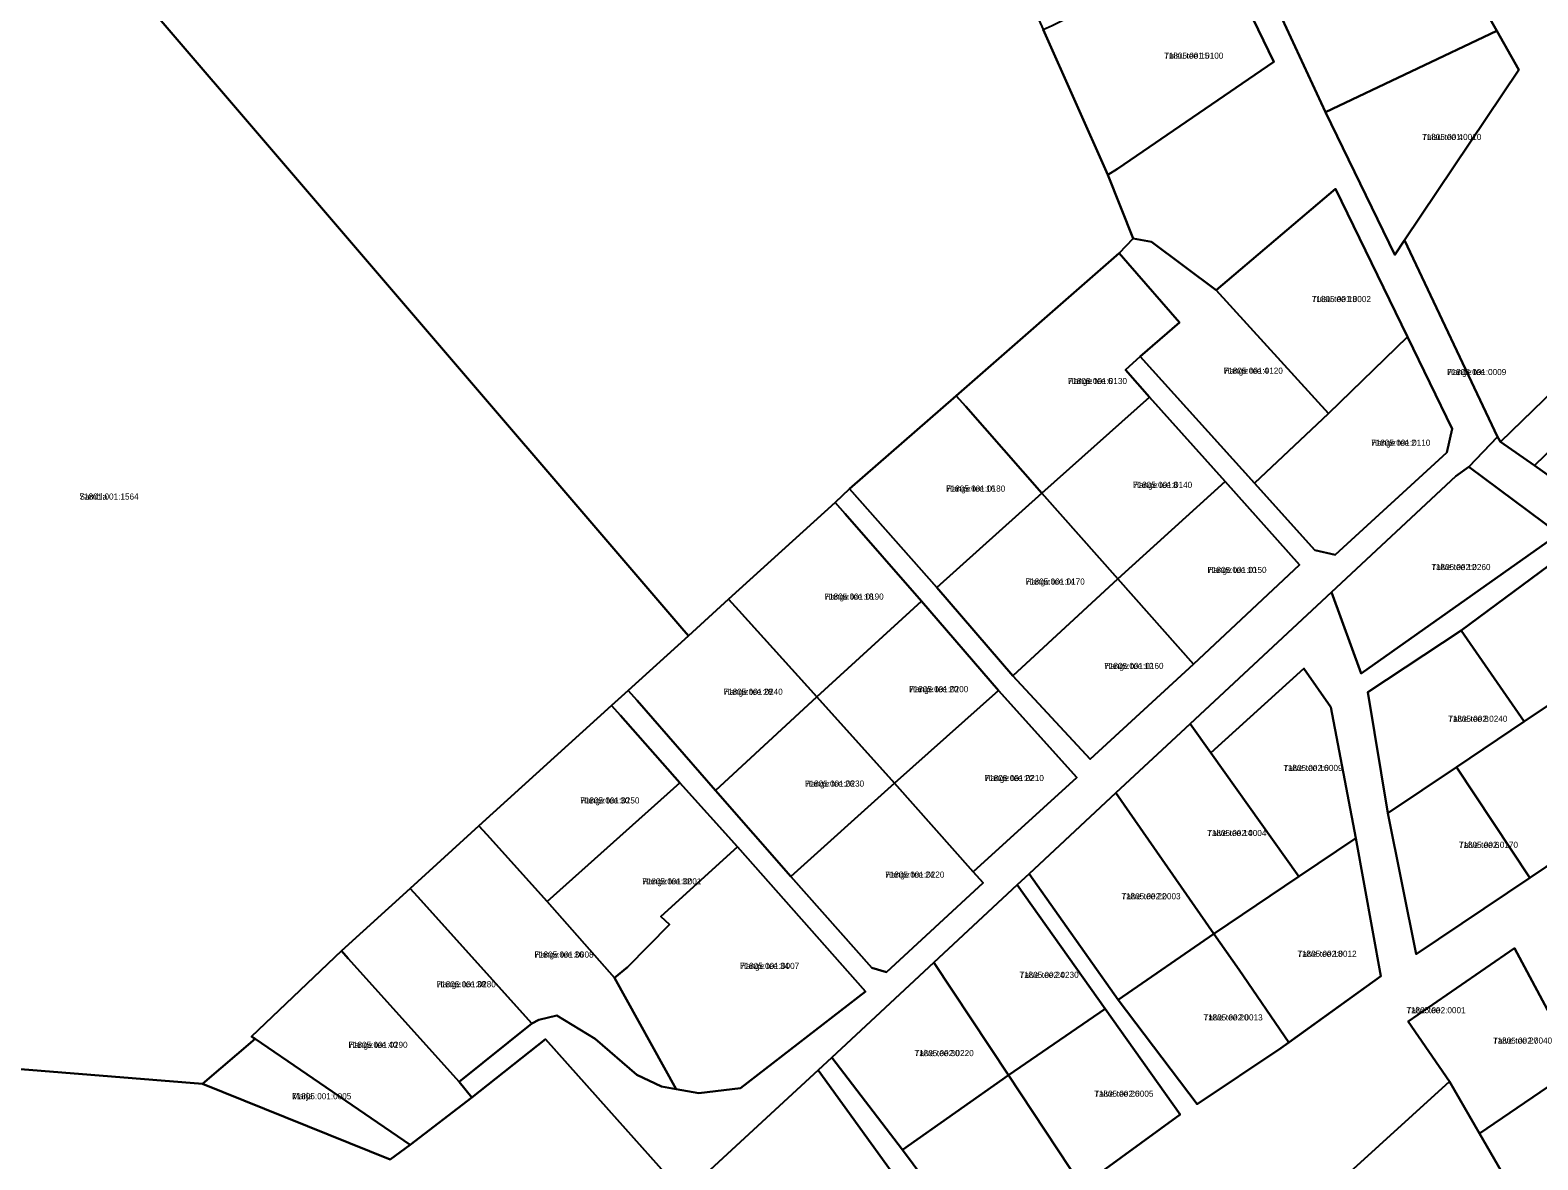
# Model space of a CAD drawing. Extents: x 529768 to 552006, y 6562269 to 6580975.
# Drawn here: x 536847 to 537216.6, y 6571536.6 to 6571813.7 of the extents above; entities that cross this region are included whole.
import ezdxf

# ---------------------------------------------------------------- set-up
doc = ezdxf.new("R2010")
doc.units = 0
for name, color, linetype in [('L_AADRESS', 7, 'Continuous'), ('PIIR', 7, 'Continuous'), ('TUNNUS', 7, 'Continuous')]:
    doc.layers.add(name, color=color, linetype=linetype)

msp = doc.modelspace()

# ---------------------------------------------------------------- linework, layer by layer
at = {"layer": 'PIIR'}
for points in [[(537096.13, 6571929.2), (537092.68, 6571927.79), (537052.16, 6571910.94), (537066.95, 6571876.5), (537076.6, 6571855.61), (537086.06, 6571834.53), (537095.28, 6571813.86), (537111.14, 6571778.21), (537117.33, 6571762.59), (537113.92, 6571759.03), (537073.99, 6571724.03), (537047.86, 6571701.19), (537044.31, 6571697.88), (537018.17, 6571674.14), (537008.32, 6571665.2), (537006.74, 6571667.02), (536853.55, 6571845.84), (536950.05, 6571943.56), (537012.05, 6572006.32), (537040.27, 6572034.93), (537094.8, 6571931.7)], [(536709.77, 6571698.43), (536853.55, 6571845.84), (537006.74, 6571667.02), (537008.32, 6571665.2), (536993.55, 6571651.78), (536989.51, 6571648.09), (536956.98, 6571618.54), (536940.14, 6571603.17), (536923.28, 6571587.88), (536901.22, 6571566.87), (536902.1, 6571566.31), (536889.2, 6571555.32), (536748.2, 6571566.65)], [(537111.14, 6571778.21), (537095.28, 6571813.86), (537097.48, 6571814.83), (537137.7, 6571835.2), (537151.88, 6571805.93), (537113.54, 6571779.72)], [(537194.25, 6571835.14), (537206.48, 6571813.58), (537164.55, 6571793.63), (537153.89, 6571816.46)], [(537207.41, 6571712.76), (537263.08, 6571766.69), (537241.8, 6571823.96), (537251.14, 6571827.4), (537271.88, 6571771.88), (537289.17, 6571751.93), (537319.33, 6571717.37), (537343.45, 6571689.67), (537363.97, 6571665.21), (537384.49, 6571640.72), (537373.73, 6571637.88), (537344.06, 6571673.39), (537325.62, 6571694.93), (537306.96, 6571716.33), (537282.48, 6571744.51), (537269.52, 6571759.13), (537215.76, 6571706.92)], [(537181.49, 6571758.59), (537164.55, 6571793.63), (537206.48, 6571813.58), (537211.88, 6571803.95), (537183.86, 6571762.17)], [(537166.97, 6571774.82), (537184.58, 6571738.54), (537165.23, 6571719.71), (537137.74, 6571749.91)], [(537128.7, 6571742.03), (537116.04, 6571756.59), (537113.92, 6571759.03), (537117.33, 6571762.59), (537121.88, 6571761.77), (537137.74, 6571749.91), (537165.23, 6571719.71), (537147.08, 6571702.64), (537119.12, 6571733.7)], [(537076.32, 6571721.39), (537073.99, 6571724.03), (537113.92, 6571759.03), (537116.04, 6571756.59), (537128.7, 6571742.03), (537119.12, 6571733.7), (537115.45, 6571730.44), (537121.36, 6571723.71), (537094.95, 6571700.12)], [(537215.76, 6571706.92), (537269.52, 6571759.13), (537282.48, 6571744.51), (537275, 6571733.97), (537262.84, 6571715.87), (537252.23, 6571699.73), (537243.84, 6571687.03)], [(537161.88, 6571686.2), (537147.08, 6571702.64), (537165.23, 6571719.71), (537184.58, 6571738.54), (537195.56, 6571715.93), (537194.24, 6571710.12), (537166.9, 6571685.05)], [(537050.33, 6571698.37), (537047.86, 6571701.19), (537073.99, 6571724.03), (537076.32, 6571721.39), (537094.95, 6571700.12), (537069.21, 6571677.04)], [(537094.95, 6571700.12), (537121.36, 6571723.71), (537139.95, 6571702.99), (537113.57, 6571679.18)], [(537165.99, 6571675.89), (537196.48, 6571704.29), (537199.69, 6571706.62), (537221.71, 6571690.16), (537173.28, 6571655.97)], [(537113.57, 6571679.18), (537139.95, 6571702.99), (537158.13, 6571682.6), (537132.18, 6571658.2)], [(537020.7, 6571671.39), (537018.17, 6571674.14), (537044.31, 6571697.88), (537046.78, 6571695.06), (537065.49, 6571673.67), (537039.81, 6571650.23)], [(537094.95, 6571700.12), (537113.57, 6571679.18), (537087.88, 6571655.34), (537069.21, 6571677.04)], [(537213.22, 6571644.15), (537197.78, 6571666.5), (537225.83, 6571687.23), (537249.86, 6571668.81), (537219.92, 6571648.65)], [(537087.88, 6571655.34), (537113.57, 6571679.18), (537132.18, 6571658.2), (537106.82, 6571634.89)], [(536995.76, 6571649.33), (536993.55, 6571651.78), (537008.32, 6571665.2), (537018.17, 6571674.14), (537020.7, 6571671.39), (537039.81, 6571650.23), (537014.94, 6571627.26)], [(537039.81, 6571650.23), (537065.49, 6571673.67), (537084.33, 6571651.77), (537058.84, 6571629.01)], [(537174.86, 6571651.39), (537197.78, 6571666.5), (537213.22, 6571644.15), (537196.65, 6571632.99), (537179.83, 6571621.66)], [(537157.94, 6571606.11), (537136.38, 6571636.49), (537159.17, 6571657.15), (537165.79, 6571647.66), (537171.99, 6571615.58)], [(537014.94, 6571627.26), (537039.81, 6571650.23), (537058.84, 6571629.01), (537033.48, 6571606.12)], [(537058.84, 6571629.01), (537084.33, 6571651.77), (537103.52, 6571630.46), (537078.12, 6571607.32)], [(536958.91, 6571616.47), (536956.98, 6571618.54), (536989.51, 6571648.09), (536991.71, 6571645.64), (537006.24, 6571629.08), (536973.7, 6571600.02)], [(537196.65, 6571632.99), (537213.22, 6571644.15), (537219.92, 6571648.65), (537238.88, 6571622.17), (537214.58, 6571605.84)], [(537137.16, 6571592.11), (537113.12, 6571626.64), (537131.33, 6571643.6), (537136.38, 6571636.49), (537157.94, 6571606.11)], [(537179.83, 6571621.66), (537196.65, 6571632.99), (537214.58, 6571605.84), (537186.72, 6571587.12)], [(536990.2, 6571581.25), (536973.7, 6571600.02), (537006.24, 6571629.08), (537020.34, 6571613.43), (537001.54, 6571596.35), (537003.66, 6571594.34), (536993.38, 6571583.88)], [(537033.48, 6571606.12), (537058.84, 6571629.01), (537078.12, 6571607.32), (537080.59, 6571604.57), (537056.93, 6571582.7), (537053.29, 6571583.77)], [(537091.83, 6571606.8), (537113.12, 6571626.64), (537137.16, 6571592.11), (537113.7, 6571575.9)], [(536969.95, 6571570.05), (536941.95, 6571601.2), (536940.14, 6571603.17), (536956.98, 6571618.54), (536958.91, 6571616.47), (536973.7, 6571600.02), (536990.2, 6571581.25), (537005.37, 6571553.97), (537001.72, 6571554.61), (536995.65, 6571557.53), (536985.49, 6571566.32), (536976.06, 6571572.02), (536971.65, 6571570.99)], [(536990.2, 6571581.25), (536993.38, 6571583.88), (537003.66, 6571594.34), (537001.54, 6571596.35), (537020.34, 6571613.43), (537051.77, 6571577.93), (537021.09, 6571554.26), (537010.85, 6571553), (537005.37, 6571553.97)], [(537137.16, 6571592.11), (537157.94, 6571606.11), (537171.99, 6571615.58), (537178.12, 6571581.73), (537155.52, 6571565.45), (537143.39, 6571583.22)], [(536923.28, 6571587.88), (536940.14, 6571603.17), (536941.95, 6571601.2), (536969.95, 6571570.05), (536952.13, 6571555.8), (536924.9, 6571586.05)], [(537068.52, 6571585.09), (537088.94, 6571604.11), (537110.48, 6571573.68), (537086.82, 6571557.38)], [(537113.7, 6571575.9), (537137.16, 6571592.11), (537143.39, 6571583.22), (537155.52, 6571565.45), (537153.57, 6571564.05), (537133.06, 6571550.29)], [(536901.22, 6571566.87), (536923.28, 6571587.88), (536924.9, 6571586.05), (536952.13, 6571555.8), (536955.2, 6571551.96), (536940.12, 6571540.34), (536902.1, 6571566.31)], [(537194.91, 6571555.85), (537184.78, 6571570.56), (537210.86, 6571588.53), (537226.38, 6571559.54), (537202.25, 6571543.14)], [(537043.51, 6571561.79), (537068.52, 6571585.09), (537086.82, 6571557.38), (537060.8, 6571539.07)], [(537110.48, 6571573.68), (537128.86, 6571547.74), (537104.77, 6571530.16), (537086.82, 6571557.38)], [(536750.24, 6571559.57), (536748.2, 6571566.65), (536889.2, 6571555.32), (536935.21, 6571536.71), (536940.12, 6571540.34), (536955.2, 6571551.96), (536973.28, 6571566.23), (536988.79, 6571548.84), (537007.19, 6571528.23), (536992.07, 6571507.56), (536981.72, 6571494), (536981.01, 6571490.97), (536976.1, 6571467.41), (536971.82, 6571443.6), (536967.33, 6571421.54), (536963.25, 6571398.53), (536958.38, 6571372.88), (536923.59, 6571358.16), (536874.33, 6571360.77), (536793, 6571361.49)], [(536902.1, 6571566.31), (536940.12, 6571540.34), (536935.21, 6571536.71), (536889.2, 6571555.32)], [(537007.19, 6571528.23), (537040.14, 6571558.66), (537059.07, 6571532.42), (537025.26, 6571508.67)], [(537060.8, 6571539.07), (537086.82, 6571557.38), (537104.77, 6571530.16), (537079.89, 6571513.53)], [(537202.25, 6571543.14), (537226.38, 6571559.54), (537243.74, 6571536.66), (537216.63, 6571518.24)], [(537168.61, 6571531.95), (537194.91, 6571555.85), (537202.25, 6571543.14), (537216.63, 6571518.24), (537219.7, 6571512.92), (537193.11, 6571492.51)]]:
    msp.add_lwpolyline(points, close=True, dxfattribs=at)
for points in [[(537153.89, 6571816.46), (537164.55, 6571793.63), (537181.49, 6571758.59), (537183.86, 6571762.17), (537206.68, 6571713.99), (537199.69, 6571706.62), (537196.48, 6571704.29), (537165.99, 6571675.89), (537131.33, 6571643.6), (537113.12, 6571626.64), (537091.83, 6571606.8), (537088.94, 6571604.11), (537068.52, 6571585.09), (537043.51, 6571561.79), (537040.14, 6571558.66), (537026.4, 6571546.01), (537007.19, 6571528.23), (536988.79, 6571548.84), (536973.28, 6571566.23), (536955.2, 6571551.96), (536952.13, 6571555.8), (536969.95, 6571570.05), (536971.65, 6571570.99), (536976.06, 6571572.02), (536985.49, 6571566.32), (536995.65, 6571557.53), (537001.72, 6571554.61), (537005.37, 6571553.97), (537010.85, 6571553), (537021.09, 6571554.26), (537051.77, 6571577.93), (537020.34, 6571613.43), (537006.24, 6571629.08), (536991.71, 6571645.64), (536989.51, 6571648.09), (536993.55, 6571651.78), (536995.76, 6571649.33), (537014.94, 6571627.26), (537033.48, 6571606.12), (537053.29, 6571583.77), (537056.93, 6571582.7), (537080.59, 6571604.57), (537078.12, 6571607.32), (537103.52, 6571630.46), (537084.33, 6571651.77), (537065.49, 6571673.67), (537046.78, 6571695.06), (537044.31, 6571697.88), (537047.86, 6571701.19), (537050.33, 6571698.37), (537069.21, 6571677.04), (537087.88, 6571655.34), (537106.82, 6571634.89), (537132.18, 6571658.2), (537158.13, 6571682.6), (537139.95, 6571702.99), (537121.36, 6571723.71), (537115.45, 6571730.44), (537119.12, 6571733.7), (537147.08, 6571702.64), (537161.88, 6571686.2), (537166.9, 6571685.05), (537194.24, 6571710.12), (537195.56, 6571715.93), (537184.58, 6571738.54), (537166.97, 6571774.82), (537137.74, 6571749.91), (537121.88, 6571761.77), (537117.33, 6571762.59), (537111.14, 6571778.21), (537113.54, 6571779.72), (537151.88, 6571805.93), (537137.7, 6571835.2)], [(537241.8, 6571823.96), (537263.08, 6571766.69), (537207.41, 6571712.76), (537206.68, 6571713.99), (537183.86, 6571762.17), (537211.88, 6571803.95), (537206.48, 6571813.58), (537194.25, 6571835.14)], [(537221.71, 6571690.16), (537199.69, 6571706.62), (537206.68, 6571713.99), (537207.41, 6571712.76), (537215.76, 6571706.92), (537243.84, 6571687.03)], [(537104.77, 6571530.16), (537128.86, 6571547.74), (537110.48, 6571573.68), (537088.94, 6571604.11), (537091.83, 6571606.8), (537113.7, 6571575.9), (537133.06, 6571550.29), (537153.57, 6571564.05), (537178.12, 6571581.73), (537171.99, 6571615.58), (537165.79, 6571647.66), (537159.17, 6571657.15), (537136.38, 6571636.49), (537131.33, 6571643.6), (537165.99, 6571675.89), (537173.28, 6571655.97), (537221.71, 6571690.16)], [(537225.83, 6571687.23), (537197.78, 6571666.5), (537174.86, 6571651.39), (537179.83, 6571621.66), (537186.72, 6571587.12), (537214.58, 6571605.84), (537238.88, 6571622.17)], [(537226.38, 6571559.54), (537210.86, 6571588.53), (537184.78, 6571570.56), (537194.91, 6571555.85), (537168.61, 6571531.95)], [(537059.07, 6571532.42), (537040.14, 6571558.66), (537043.51, 6571561.79), (537060.8, 6571539.07), (537079.89, 6571513.53)]]:
    msp.add_lwpolyline(points, dxfattribs=at)

# ---------------------------------------------------------------- texts
at = {"layer": 'L_AADRESS'}
for s, p in [('Tuisu tee 15', (537124.98, 6571806.71)), ('Tuisu tee 4', (537188.21, 6571786.78)), ('Tuisu tee 13', (537161.16, 6571747.02)), ('Hange tee 4', (537139.57, 6571729.44)), ('Hange tee 6', (537101.35, 6571726.92)), ('Hange tee', (537194.33, 6571729.12)), ('Hange tee 2', (537175.72, 6571711.79)), ('Hange tee 16', (537071.51, 6571700.54)), ('Hange tee 8', (537117.34, 6571701.45)), ('Sambla', (536859.05, 6571698.58)), ('Talve tee 12', (537190.47, 6571681.29)), ('Hange tee 14', (537090.99, 6571677.73)), ('Hange tee 10', (537135.57, 6571680.59)), ('Hange tee 18', (537041.7, 6571674.05)), ('Hange tee 12', (537110.31, 6571657.04)), ('Hange tee 28', (537016.95, 6571650.7)), ('Hange tee 20', (537062.44, 6571651.34)), ('Talve tee 8', (537194.6, 6571644.08)), ('Hange tee 22', (537080.98, 6571629.54)), ('Talve tee 16', (537154.19, 6571632.02)), ('Hange tee 26', (537036.92, 6571628.18)), ('Hange tee 30', (536981.83, 6571624.05)), ('Talve tee 14', (537135.53, 6571616.07)), ('Talve tee 6', (537197.2, 6571613.16)), ('Hange tee 32', (536997.02, 6571604.21)), ('Hange tee 24', (537056.58, 6571605.86)), ('Talve tee 22', (537114.49, 6571600.56)), ('Hange tee 36', (536970.59, 6571586.25)), ('Talve tee 18', (537157.64, 6571586.44)), ('Hange tee 34', (537020.99, 6571583.47)), ('Hange tee 38', (536946.62, 6571578.97)), ('Talve tee 24', (537089.5, 6571581.27)), ('Talve tee 20', (537134.61, 6571570.84)), ('Talve tee', (537184.36, 6571572.61)), ('Hange tee 40', (536924.99, 6571564.11)), ('Talve tee 27', (537205.58, 6571565.15)), ('Talve tee 30', (537063.77, 6571562.08)), ('Talve tee 26', (537107.84, 6571552.13)), ('Marja', (536911.19, 6571551.51))]:
    msp.add_text(s, height=1.5, dxfattribs=at).set_placement(p)
at = {"layer": 'TUNNUS'}
for s, p in [('71805:001:0100', (537124.98, 6571806.71)), ('71805:001:0010', (537188.21, 6571786.78)), ('71805:001:0002', (537161.16, 6571747.02)), ('71805:001:0120', (537139.57, 6571729.44)), ('71805:001:0130', (537101.35, 6571726.92)), ('71805:001:0009', (537194.33, 6571729.12)), ('71805:001:0110', (537175.72, 6571711.79)), ('71805:001:0180', (537071.51, 6571700.54)), ('71805:001:0140', (537117.34, 6571701.45)), ('71801:001:1564', (536859.05, 6571698.58)), ('71805:002:0260', (537190.47, 6571681.29)), ('71805:001:0170', (537090.99, 6571677.73)), ('71805:001:0150', (537135.57, 6571680.59)), ('71805:001:0190', (537041.7, 6571674.05)), ('71805:001:0160', (537110.31, 6571657.04)), ('71805:001:0240', (537016.95, 6571650.7)), ('71805:001:0200', (537062.44, 6571651.34)), ('71805:002:0240', (537194.6, 6571644.08)), ('71805:001:0210', (537080.98, 6571629.54)), ('71805:002:0009', (537154.19, 6571632.02)), ('71805:001:0230', (537036.92, 6571628.18)), ('71805:001:0250', (536981.83, 6571624.05)), ('71805:002:0004', (537135.53, 6571616.07)), ('71805:002:0170', (537197.2, 6571613.16)), ('71805:001:0001', (536997.02, 6571604.21)), ('71805:001:0220', (537056.58, 6571605.86)), ('71805:002:0003', (537114.49, 6571600.56)), ('71805:001:0008', (536970.59, 6571586.25)), ('71805:002:0012', (537157.64, 6571586.44)), ('71805:001:0007', (537020.99, 6571583.47)), ('71805:001:0280', (536946.62, 6571578.97)), ('71805:002:0230', (537089.5, 6571581.27)), ('71805:002:0013', (537134.61, 6571570.84)), ('71805:002:0001', (537184.36, 6571572.61)), ('71805:001:0290', (536924.99, 6571564.11)), ('71805:002:0040', (537205.58, 6571565.15)), ('71805:002:0220', (537063.77, 6571562.08)), ('71805:002:0005', (537107.84, 6571552.13)), ('71805:001:0005', (536911.19, 6571551.51))]:
    msp.add_text(s, height=1.5, dxfattribs=at).set_placement(p)

doc.saveas('drawing.dxf')
